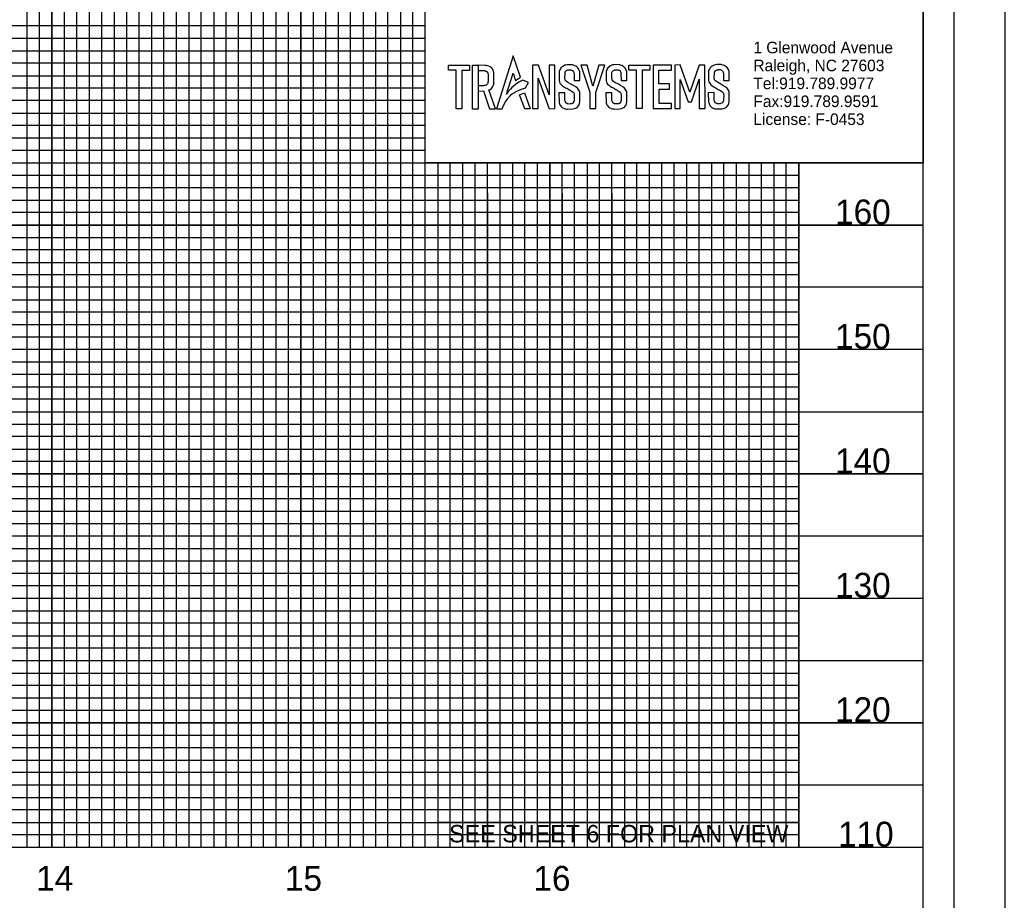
# Model space of a CAD drawing. Extents: x 1779926 to 1781626, y 618464 to 619564.
# Drawn here: x 1781230 to 1781626, y 619017.9 to 619371.7 of the extents above; entities that cross this region are included whole.
import ezdxf

# ---------------------------------------------------------------- set-up
doc = ezdxf.new("R2010")
doc.units = 0
for name, color, linetype in [('Default', 7, 'Continuous'), ('Exist Vertical Profile Horizontal Axis Label Major', 7, 'Continuous'), ('Exist Vertical Profile Vertical Axis Label', 7, 'Continuous'), ('Old_Level_2', 7, 'Continuous'), ('Old_Level_58', 7, 'Continuous'), ('Prop DSN Text', 7, 'Continuous'), ('Prop Grid Mask', 7, 'Continuous'), ('Sheet DOT Grid CELL', 7, 'Continuous'), ('Sheet Layout Profile Border Port 1', 7, 'Continuous'), ('Sheet Plot Border Inside CELL', 7, 'Continuous'), ('Sheet Plot Border Outside CELL', 7, 'Continuous'), ('Sheet Profile CELL', 7, 'Continuous'), ('Sheet Profile Grid Major CELL', 7, 'Continuous'), ('Sheet Profile Grid Middle CELL', 7, 'Continuous'), ('Sheet Profile Grid Minor CELL', 7, 'Continuous')]:
    doc.layers.add(name, color=color, linetype=linetype)

msp = doc.modelspace()

# ---------------------------------------------------------------- linework, layer by layer
at = {"layer": 'Default'}
for points in [[(1781428.26, 619357.23), (1781421.6, 619335.89), (1781423.82, 619335.9), (1781424.16, 619336.74), (1781424.73, 619337.9), (1781425.05, 619338.53), (1781425.42, 619339.07), (1781425.95, 619339.83), (1781426.27, 619340.3), (1781426.65, 619340.69), (1781427.03, 619341.08), (1781427.52, 619341.58), (1781427.93, 619341.85), (1781428.34, 619342.18), (1781428.9, 619342.5), (1781429.39, 619342.78), (1781430.61, 619343.35), (1781431.61, 619343.76), (1781433.25, 619344.32), (1781434.39, 619346.46), (1781432.21, 619347.42), (1781430.58, 619346.53), (1781429.2, 619345.63), (1781428.22, 619344.83), (1781427.7, 619344.41), (1781427.17, 619343.84), (1781426.63, 619343.27), (1781426.23, 619342.85), (1781425.85, 619342.2), (1781425.65, 619341.84), (1781428.27, 619350.22), (1781429.27, 619347.33), (1781431.17, 619348.58)], [(1781402.3, 619353.38), (1781410.76, 619353.39), (1781410.77, 619351.31), (1781407.66, 619351.31), (1781407.67, 619335.89), (1781405.32, 619335.89), (1781405.31, 619351.41), (1781402.33, 619351.41)], [(1781411.92, 619353.37), (1781414.23, 619353.38), (1781414.25, 619335.81), (1781411.93, 619335.81)], [(1781414.24, 619351.29), (1781416.62, 619351.29), (1781416.93, 619351.24), (1781417.33, 619351.08), (1781417.65, 619350.86), (1781417.88, 619350.59), (1781418.04, 619350.26), (1781418.16, 619350), (1781418.16, 619349.42), (1781418.17, 619346.93), (1781418.11, 619346.6), (1781418.03, 619346.16), (1781417.89, 619345.86), (1781417.69, 619345.6), (1781417.43, 619345.39), (1781417, 619345.24), (1781416.67, 619345.2), (1781416.35, 619345.15), (1781414.24, 619345.14), (1781414.25, 619343.03), (1781416.36, 619343.05), (1781418.73, 619335.88), (1781421.14, 619335.91), (1781418.49, 619343.45), (1781418.87, 619343.58), (1781419.41, 619343.98), (1781419.9, 619344.52), (1781420.25, 619345.15), (1781420.46, 619345.78), (1781420.45, 619345.97), (1781420.49, 619350.53), (1781420.28, 619351.28), (1781419.92, 619351.96), (1781419.51, 619352.43), (1781418.81, 619352.9), (1781418.14, 619353.13), (1781417.46, 619353.35), (1781417.05, 619353.35), (1781414.23, 619353.38)], [(1781436.03, 619353.41), (1781436.05, 619335.95), (1781438.28, 619335.95), (1781438.27, 619348.23), (1781442.72, 619335.93), (1781444.97, 619335.96), (1781444.95, 619353.46), (1781442.77, 619353.46), (1781442.79, 619341.48), (1781438.39, 619353.42)], [(1781452.73, 619347.24), (1781455.04, 619347.24), (1781455.04, 619350.72), (1781454.84, 619351.42), (1781454.56, 619352.01), (1781454.26, 619352.4), (1781453.89, 619352.76), (1781453.45, 619353.04), (1781453.03, 619353.21), (1781453.03, 619353.21), (1781452.57, 619353.41), (1781452.08, 619353.53), (1781451.76, 619353.61), (1781450.01, 619353.57), (1781449.48, 619353.48), (1781449.03, 619353.4), (1781448.57, 619353.16), (1781448.16, 619352.95), (1781447.77, 619352.67), (1781447.46, 619352.35), (1781447.22, 619351.99), (1781447.02, 619351.59), (1781446.77, 619350.9), (1781446.72, 619350.38), (1781446.72, 619347.21), (1781446.83, 619346.74), (1781447.06, 619346.24), (1781447.35, 619345.83), (1781447.65, 619345.52), (1781448.1, 619345.17), (1781448.55, 619344.83), (1781448.83, 619344.61), (1781449.32, 619344.38), (1781449.8, 619344.16), (1781450.19, 619343.9), (1781450.63, 619343.62), (1781451.16, 619343.35), (1781451.59, 619343.13), (1781452.02, 619342.82), (1781452.33, 619342.52), (1781452.58, 619342.28), (1781452.73, 619341.8), (1781452.83, 619341.5), (1781452.79, 619339.27), (1781452.63, 619338.78), (1781452.39, 619338.36), (1781452.06, 619338.07), (1781451.71, 619337.91), (1781451.36, 619337.84), (1781450.4, 619337.82), (1781450.08, 619337.91), (1781449.75, 619338.1), (1781449.42, 619338.3), (1781449.28, 619338.63), (1781449.14, 619338.97), (1781449.02, 619339.23), (1781448.99, 619342.35), (1781446.65, 619342.32), (1781446.69, 619338.61), (1781446.81, 619338.33), (1781447.08, 619337.46), (1781447.26, 619337.17), (1781447.51, 619336.85), (1781447.89, 619336.48), (1781448.19, 619336.29), (1781448.63, 619336.1), (1781448.79, 619336.04), (1781449.22, 619335.86), (1781449.75, 619335.8), (1781450.14, 619335.76), (1781452.29, 619335.82), (1781452.88, 619335.96), (1781453.71, 619336.33), (1781453.99, 619336.46), (1781454.61, 619337.25), (1781454.94, 619338.04), (1781455.1, 619338.75), (1781455.04, 619342.17), (1781455.04, 619342.64), (1781454.91, 619343.02), (1781454.71, 619343.37), (1781454.17, 619344.13), (1781453.47, 619344.69), (1781452.49, 619345.27), (1781451.75, 619345.71), (1781450.28, 619346.48), (1781449.53, 619347.04), (1781449.2, 619347.46), (1781449.12, 619347.74), (1781449.05, 619348.03), (1781449.09, 619350.46), (1781449.22, 619350.71), (1781449.34, 619350.97), (1781449.52, 619351.12), (1781449.75, 619351.32), (1781450.01, 619351.42), (1781450.27, 619351.53), (1781450.41, 619351.5), (1781450.43, 619351.58), (1781451.39, 619351.56), (1781451.67, 619351.45), (1781451.94, 619351.34), (1781452.22, 619351.23), (1781452.35, 619351.04), (1781452.53, 619350.76), (1781452.63, 619350.48), (1781452.72, 619350.21), (1781452.71, 619349.9)], [(1781458, 619353.42), (1781455.46, 619353.42), (1781459.08, 619342.54), (1781459.11, 619335.99), (1781461.5, 619336.01), (1781461.47, 619342.5), (1781465.13, 619353.46), (1781462.63, 619353.39), (1781460.33, 619345.05)], [(1781471.6, 619347.26), (1781473.91, 619347.26), (1781473.91, 619350.74), (1781473.71, 619351.44), (1781473.43, 619352.03), (1781473.13, 619352.42), (1781472.76, 619352.77), (1781472.32, 619353.06), (1781471.9, 619353.23), (1781471.9, 619353.23), (1781471.44, 619353.42), (1781470.96, 619353.55), (1781470.64, 619353.63), (1781468.89, 619353.59), (1781468.36, 619353.5), (1781467.9, 619353.42), (1781467.44, 619353.18), (1781467.03, 619352.97), (1781466.64, 619352.68), (1781466.33, 619352.37), (1781466.09, 619352.01), (1781465.89, 619351.61), (1781465.64, 619350.91), (1781465.59, 619350.4), (1781465.59, 619347.23), (1781465.7, 619346.75), (1781465.93, 619346.26), (1781466.22, 619345.85), (1781466.52, 619345.54), (1781466.97, 619345.19), (1781467.42, 619344.84), (1781467.71, 619344.62), (1781468.19, 619344.4), (1781468.67, 619344.17), (1781469.06, 619343.92), (1781469.5, 619343.63), (1781470.03, 619343.37), (1781470.46, 619343.15), (1781470.89, 619342.83), (1781471.2, 619342.54), (1781471.45, 619342.3), (1781471.61, 619341.82), (1781471.7, 619341.52), (1781471.67, 619339.28), (1781471.51, 619338.8), (1781471.26, 619338.38), (1781470.93, 619338.09), (1781470.58, 619337.93), (1781470.24, 619337.86), (1781469.27, 619337.84), (1781468.95, 619337.93), (1781468.62, 619338.12), (1781468.29, 619338.31), (1781468.15, 619338.65), (1781468.01, 619338.98), (1781467.9, 619339.25), (1781467.86, 619342.36), (1781465.52, 619342.34), (1781465.57, 619338.63), (1781465.68, 619338.34), (1781465.95, 619337.48), (1781466.13, 619337.19), (1781466.38, 619336.87), (1781466.76, 619336.5), (1781467.07, 619336.3), (1781467.5, 619336.12), (1781467.66, 619336.05), (1781468.09, 619335.87), (1781468.62, 619335.82), (1781469.02, 619335.78), (1781471.16, 619335.84), (1781471.75, 619335.98), (1781472.58, 619336.35), (1781472.86, 619336.48), (1781473.48, 619337.27), (1781473.81, 619338.05), (1781473.97, 619338.76), (1781473.92, 619342.19), (1781473.91, 619342.66), (1781473.78, 619343.03), (1781473.59, 619343.39), (1781473.05, 619344.15), (1781472.34, 619344.7), (1781471.36, 619345.28), (1781470.62, 619345.73), (1781469.16, 619346.49), (1781468.4, 619347.06), (1781468.07, 619347.48), (1781468, 619347.76), (1781467.92, 619348.05), (1781467.96, 619350.48), (1781468.09, 619350.73), (1781468.21, 619350.99), (1781468.39, 619351.14), (1781468.62, 619351.33), (1781468.88, 619351.44), (1781469.14, 619351.55), (1781469.29, 619351.52), (1781469.3, 619351.59), (1781470.26, 619351.58), (1781470.54, 619351.47), (1781470.81, 619351.36), (1781471.09, 619351.25), (1781471.22, 619351.06), (1781471.41, 619350.78), (1781471.5, 619350.5), (1781471.59, 619350.23), (1781471.58, 619349.92)], [(1781474.76, 619353.45), (1781483.22, 619353.45), (1781483.23, 619351.38), (1781480.12, 619351.38), (1781480.13, 619335.96), (1781477.78, 619335.95), (1781477.77, 619351.48), (1781474.79, 619351.48)], [(1781491.83, 619353.45), (1781484.44, 619353.45), (1781484.46, 619336.02), (1781491.93, 619336.03), (1781491.93, 619338), (1781486.88, 619337.99), (1781486.88, 619343.84), (1781491.1, 619343.84), (1781491.09, 619345.91), (1781486.84, 619345.91), (1781486.84, 619351.41), (1781491.85, 619351.41)], [(1781499.21, 619342.6), (1781495.39, 619353.53), (1781493.18, 619353.42), (1781493.27, 619335.96), (1781495.38, 619335.97), (1781495.32, 619347.65), (1781498.59, 619338.66), (1781499.93, 619338.63), (1781503, 619347.76), (1781503.05, 619336.04), (1781505.33, 619336.05), (1781505.26, 619353.47), (1781502.96, 619353.46)], [(1781512.73, 619347.3), (1781515.04, 619347.3), (1781515.04, 619350.77), (1781514.84, 619351.48), (1781514.56, 619352.07), (1781514.26, 619352.46), (1781513.89, 619352.81), (1781513.46, 619353.09), (1781513.03, 619353.27), (1781513.03, 619353.27), (1781512.57, 619353.46), (1781512.09, 619353.58), (1781511.77, 619353.66), (1781510.02, 619353.63), (1781509.49, 619353.54), (1781509.03, 619353.46), (1781508.57, 619353.22), (1781508.17, 619353.01), (1781507.77, 619352.72), (1781507.46, 619352.41), (1781507.22, 619352.04), (1781507.03, 619351.65), (1781506.77, 619350.95), (1781506.72, 619350.44), (1781506.72, 619347.27), (1781506.84, 619346.79), (1781507.07, 619346.3), (1781507.35, 619345.89), (1781507.65, 619345.58), (1781508.1, 619345.23), (1781508.55, 619344.88), (1781508.84, 619344.66), (1781509.32, 619344.44), (1781509.8, 619344.21), (1781510.19, 619343.96), (1781510.64, 619343.67), (1781511.16, 619343.41), (1781511.6, 619343.19), (1781512.03, 619342.87), (1781512.34, 619342.58), (1781512.59, 619342.34), (1781512.74, 619341.86), (1781512.83, 619341.56), (1781512.8, 619339.32), (1781512.64, 619338.84), (1781512.39, 619338.42), (1781512.06, 619338.13), (1781511.71, 619337.97), (1781511.37, 619337.9), (1781510.41, 619337.88), (1781510.08, 619337.97), (1781509.76, 619338.16), (1781509.43, 619338.35), (1781509.28, 619338.69), (1781509.14, 619339.02), (1781509.03, 619339.29), (1781508.99, 619342.4), (1781506.65, 619342.37), (1781506.7, 619338.66), (1781506.82, 619338.38), (1781507.09, 619337.52), (1781507.26, 619337.23), (1781507.51, 619336.91), (1781507.89, 619336.53), (1781508.2, 619336.34), (1781508.63, 619336.16), (1781508.79, 619336.09), (1781509.22, 619335.91), (1781509.76, 619335.86), (1781510.15, 619335.82), (1781512.29, 619335.87), (1781512.89, 619336.01), (1781513.71, 619336.39), (1781513.99, 619336.51), (1781514.61, 619337.31), (1781514.95, 619338.09), (1781515.1, 619338.8), (1781515.05, 619342.22), (1781515.04, 619342.7), (1781514.91, 619343.07), (1781514.72, 619343.43), (1781514.18, 619344.19), (1781513.47, 619344.74), (1781512.5, 619345.32), (1781511.75, 619345.77), (1781510.29, 619346.53), (1781509.53, 619347.09), (1781509.21, 619347.52), (1781509.13, 619347.8), (1781509.05, 619348.08), (1781509.1, 619350.51), (1781509.22, 619350.77), (1781509.34, 619351.02), (1781509.52, 619351.18), (1781509.75, 619351.37), (1781510.01, 619351.48), (1781510.27, 619351.59), (1781510.42, 619351.56), (1781510.43, 619351.63), (1781511.39, 619351.62), (1781511.67, 619351.51), (1781511.95, 619351.4), (1781512.22, 619351.29), (1781512.35, 619351.09), (1781512.54, 619350.82), (1781512.63, 619350.54), (1781512.72, 619350.26), (1781512.72, 619349.96)], [(1781430.87, 619341.52), (1781432.79, 619342.29), (1781435.06, 619335.85), (1781432.95, 619335.93)]]:
    msp.add_lwpolyline(points, close=True, dxfattribs=at)
at = {"layer": 'Old_Level_58'}
for points in [[(1781392.9, 619378.14), (1781592.96, 619378.14), (1781592.96, 619314.19), (1781392.9, 619314.19)], [(1781392.96, 619378.14), (1781592.96, 619378.14), (1781592.96, 619314.19), (1781392.96, 619314.19)]]:
    msp.add_lwpolyline(points, close=True, dxfattribs=at)
at = {"layer": 'Prop Grid Mask'}
msp.add_lwpolyline([(1781542.96, 619049.19), (1781397.96, 619049.19), (1781397.96, 619039.19), (1781542.96, 619039.19)], close=True, dxfattribs=at)
at = {"layer": 'Sheet DOT Grid CELL'}
for p, q in [((1781242.96, 619039.19), (1781242.96, 619539.19)), ((1781292.96, 619039.19), (1781292.96, 619539.19)), ((1781342.96, 619039.19), (1781342.96, 619539.19)), ((1781392.96, 619039.19), (1781392.96, 619401.64)), ((1781392.91, 619339.19), (1780092.96, 619339.19)), ((1781442.96, 619039.19), (1781442.96, 619314.19)), ((1781492.96, 619039.19), (1781492.96, 619314.19)), ((1781542.96, 619039.19), (1781542.96, 619314.19)), ((1781592.96, 619289.19), (1780092.96, 619289.19)), ((1781592.96, 619239.19), (1780092.96, 619239.19)), ((1781592.96, 619189.19), (1780092.96, 619189.19)), ((1781592.96, 619139.19), (1780092.96, 619139.19)), ((1781592.96, 619089.19), (1780092.96, 619089.19))]:
    msp.add_line(p, q, dxfattribs=at)
at = {"layer": 'Sheet Layout Profile Border Port 1'}
msp.add_line((1781542.96, 619049.19), (1781542.96, 619099.19), dxfattribs=at)
for points in [[(1781542.96, 619099.19), (1781542.96, 619314.19), (1781392.91, 619314.19), (1781392.96, 619539.19), (1780142.96, 619539.19), (1780142.96, 619039.19), (1781542.96, 619039.19), (1781542.96, 619049.19)], [(1780142.96, 619378.14), (1780142.96, 619039.19), (1781542.96, 619039.19), (1781542.96, 619314.19)]]:
    msp.add_lwpolyline(points, dxfattribs=at)
at = {"layer": 'Sheet Plot Border Inside CELL'}
msp.add_lwpolyline([(1779938.96, 618486.64), (1781605.46, 618486.64), (1781605.46, 619541.74), (1779938.96, 619541.74)], close=True, dxfattribs=at)
at = {"layer": 'Sheet Plot Border Outside CELL'}
msp.add_lwpolyline([(1779925.96, 618464.19), (1781625.96, 618464.19), (1781625.96, 619564.19), (1779925.96, 619564.19)], close=True, dxfattribs=at)
at = {"layer": 'Sheet Profile CELL'}
msp.add_line((1780092.96, 619039.19), (1781592.96, 619039.19), dxfattribs=at)
msp.add_lwpolyline([(1781592.96, 619539.19), (1780092.96, 619539.19), (1780092.96, 618489.19), (1781592.96, 618489.19)], close=True, dxfattribs=at)
at = {"layer": 'Sheet Profile Grid Major CELL'}
for points in [[(1780842.96, 619039.19), (1780892.96, 619039.19), (1780892.96, 619539.19), (1780942.96, 619539.19), (1780942.96, 619039.19), (1780992.96, 619039.19), (1780992.96, 619539.19), (1781042.96, 619539.19), (1781042.96, 619039.19), (1781092.96, 619039.19), (1781092.96, 619539.19), (1781142.96, 619539.19), (1781142.96, 619039.19), (1781192.96, 619039.19), (1781192.96, 619539.19), (1781242.96, 619539.19), (1781242.96, 619039.19), (1781292.96, 619039.19), (1781292.96, 619539.19), (1781342.96, 619539.19), (1781342.96, 619039.19), (1781392.96, 619039.19), (1781392.96, 619539.19), (1781419.26, 619539.19)], [(1781542.96, 619314.19), (1781542.96, 619039.19), (1781592.96, 619039.19), (1781592.96, 619389.19)], [(1781392.96, 619339.19), (1780092.96, 619339.19), (1780092.96, 619289.19), (1781592.96, 619289.19)], [(1781442.96, 619314.19), (1781442.96, 619039.19), (1781492.96, 619039.19), (1781492.96, 619039.19), (1781492.96, 619314.19)], [(1781592.96, 619239.19), (1780092.96, 619239.19), (1780092.96, 619189.19), (1781592.96, 619189.19)], [(1781592.96, 619139.19), (1780092.96, 619139.19), (1780092.96, 619139.19), (1780092.96, 619089.19), (1781592.96, 619089.19)]]:
    msp.add_lwpolyline(points, dxfattribs=at)
at = {"layer": 'Sheet Profile Grid Middle CELL'}
for points in [[(1781217.96, 619539.19), (1781267.96, 619539.19), (1781267.96, 619039.19), (1781317.96, 619039.19), (1781317.96, 619539.19), (1781367.96, 619539.19), (1781367.96, 619039.19), (1781417.96, 619039.19), (1781417.96, 619314.19)], [(1781392.91, 619364.19), (1780092.96, 619364.19), (1780092.96, 619314.19), (1781417.96, 619314.19)], [(1781417.96, 619314.19), (1781592.96, 619314.19)], [(1781417.96, 619301.99), (1781417.96, 619039.19), (1781467.96, 619039.19), (1781467.96, 619314.19)], [(1781467.96, 619301.99), (1781467.96, 619039.19), (1781517.96, 619039.19), (1781517.96, 619314.19)], [(1781592.96, 619264.19), (1780092.96, 619264.19), (1780092.96, 619214.19), (1781592.96, 619214.19)], [(1781592.96, 619164.19), (1780092.96, 619164.19), (1780092.96, 619114.19), (1781592.96, 619114.19)], [(1781592.96, 619064.19), (1780092.96, 619064.19)]]:
    msp.add_lwpolyline(points, dxfattribs=at)
at = {"layer": 'Sheet Profile Grid Minor CELL'}
for p, q in [((1781392.91, 619354.19), (1780142.96, 619354.19)), ((1780142.96, 619349.19), (1781392.91, 619349.19)), ((1781392.91, 619329.19), (1780142.96, 619329.19)), ((1780142.96, 619324.19), (1781392.91, 619324.19)), ((1781542.96, 619304.19), (1780142.96, 619304.19)), ((1780142.96, 619299.19), (1781542.96, 619299.19)), ((1781542.96, 619294.19), (1780142.96, 619294.19)), ((1780142.96, 619284.19), (1781542.96, 619284.19)), ((1781542.96, 619279.19), (1780142.96, 619279.19)), ((1780142.96, 619274.19), (1781542.96, 619274.19)), ((1781542.96, 619269.19), (1780142.96, 619269.19)), ((1780142.96, 619259.19), (1781542.96, 619259.19)), ((1781542.96, 619254.19), (1780142.96, 619254.19)), ((1780142.96, 619249.19), (1781542.96, 619249.19)), ((1781542.96, 619244.19), (1780142.96, 619244.19)), ((1780142.96, 619234.19), (1781542.96, 619234.19)), ((1781542.96, 619229.19), (1780142.96, 619229.19)), ((1780142.96, 619224.19), (1781542.96, 619224.19)), ((1781542.96, 619219.19), (1780142.96, 619219.19)), ((1780142.96, 619209.19), (1781542.96, 619209.19)), ((1781542.96, 619204.19), (1780142.96, 619204.19)), ((1780142.96, 619199.19), (1781542.96, 619199.19)), ((1781542.96, 619194.19), (1780142.96, 619194.19)), ((1780142.96, 619184.19), (1781542.96, 619184.19)), ((1781542.96, 619179.19), (1780142.96, 619179.19)), ((1780142.96, 619174.19), (1781542.96, 619174.19)), ((1781542.96, 619169.19), (1780142.96, 619169.19)), ((1780142.96, 619159.19), (1781542.96, 619159.19)), ((1781542.96, 619154.19), (1780142.96, 619154.19)), ((1781542.96, 619149.19), (1780142.96, 619149.19)), ((1781542.96, 619144.19), (1780142.96, 619144.19)), ((1780142.96, 619134.19), (1781542.96, 619134.19)), ((1781542.96, 619129.19), (1780142.96, 619129.19)), ((1780142.96, 619124.19), (1781542.96, 619124.19)), ((1781542.96, 619119.19), (1780142.96, 619119.19)), ((1780142.96, 619109.19), (1781542.96, 619109.19)), ((1781542.96, 619104.19), (1780142.96, 619104.19)), ((1780142.96, 619099.19), (1781542.96, 619099.19)), ((1781542.96, 619094.19), (1780142.96, 619094.19)), ((1780142.96, 619084.19), (1781542.96, 619084.19)), ((1781542.96, 619079.19), (1780142.96, 619079.19)), ((1780142.96, 619074.19), (1781542.96, 619074.19)), ((1781542.96, 619069.19), (1780142.96, 619069.19)), ((1780142.96, 619059.19), (1781542.96, 619059.19)), ((1781542.96, 619054.19), (1780142.96, 619054.19)), ((1780142.96, 619049.19), (1781542.96, 619049.19))]:
    msp.add_line(p, q, dxfattribs=at)
for points in [[(1781227.96, 619539.19), (1781232.96, 619539.19), (1781232.96, 619039.19), (1781237.96, 619039.19), (1781237.96, 619539.19), (1781247.96, 619539.19), (1781247.96, 619039.19), (1781252.96, 619039.19), (1781252.96, 619539.19), (1781257.96, 619539.19), (1781257.96, 619039.19), (1781262.96, 619039.19), (1781262.96, 619539.19), (1781272.96, 619539.19), (1781272.96, 619039.19), (1781277.96, 619039.19), (1781277.96, 619539.19), (1781282.96, 619539.19), (1781282.96, 619039.19)], [(1781282.96, 619039.19), (1781287.96, 619039.19), (1781287.96, 619539.19)], [(1781297.96, 619539.19), (1781297.96, 619039.19), (1781302.96, 619039.19), (1781302.96, 619539.19)], [(1781307.96, 619539.19), (1781307.96, 619039.19), (1781312.96, 619039.19), (1781312.96, 619539.19)], [(1781322.96, 619539.19), (1781322.96, 619039.19), (1781327.96, 619039.19), (1781327.96, 619539.19)], [(1781332.96, 619539.19), (1781332.96, 619039.19), (1781337.96, 619039.19), (1781337.96, 619539.19)], [(1781347.96, 619539.19), (1781347.96, 619039.19), (1781352.96, 619039.19), (1781352.96, 619539.19)], [(1781357.96, 619539.19), (1781357.96, 619039.19), (1781362.96, 619039.19), (1781362.96, 619539.19)], [(1781372.96, 619539.19), (1781372.96, 619039.19), (1781377.96, 619039.19), (1781377.96, 619539.19)], [(1781382.96, 619539.19), (1781382.96, 619039.19), (1781387.96, 619039.19), (1781387.96, 619539.19)], [(1781392.91, 619369.19), (1780142.96, 619369.19), (1780142.96, 619359.19), (1781392.91, 619359.19)], [(1781392.91, 619344.19), (1780142.96, 619344.19), (1780142.96, 619334.19), (1781392.91, 619334.19)], [(1781392.91, 619319.19), (1780142.96, 619319.19), (1780142.96, 619309.19), (1781542.96, 619309.19)], [(1781397.96, 619314.19), (1781397.96, 619039.19), (1781402.96, 619039.19), (1781402.96, 619314.19)], [(1781407.96, 619314.19), (1781407.96, 619039.19), (1781412.96, 619039.19), (1781412.96, 619314.19)], [(1781422.96, 619314.19), (1781422.96, 619039.19), (1781422.96, 619039.19), (1781427.96, 619039.19), (1781432.96, 619039.19), (1781432.96, 619314.19)], [(1781427.96, 619314.19), (1781427.96, 619039.19)], [(1781437.94, 619314.19), (1781437.86, 619039.24), (1781442.86, 619039.24), (1781447.96, 619039.19), (1781447.96, 619314.19)], [(1781447.96, 619301.99), (1781447.96, 619039.19), (1781452.96, 619039.19), (1781452.96, 619314.19)], [(1781457.96, 619314.19), (1781457.96, 619039.19), (1781462.96, 619039.19), (1781462.96, 619314.19)], [(1781472.96, 619314.19), (1781472.96, 619039.19), (1781477.96, 619039.19), (1781477.96, 619314.19)], [(1781482.96, 619314.19), (1781482.96, 619039.19), (1781487.96, 619039.19), (1781487.96, 619314.19)], [(1781497.96, 619314.19), (1781497.96, 619039.19), (1781502.96, 619039.19), (1781502.96, 619314.19)], [(1781507.96, 619314.19), (1781507.96, 619039.19), (1781512.96, 619039.19), (1781512.96, 619314.19)], [(1781522.96, 619314.19), (1781522.96, 619039.19), (1781527.96, 619039.19), (1781527.96, 619314.19)], [(1781532.96, 619314.19), (1781532.96, 619039.19), (1781537.96, 619039.19), (1781537.96, 619314.19)], [(1781542.96, 619044.19), (1780142.96, 619044.19)]]:
    msp.add_lwpolyline(points, dxfattribs=at)

# ---------------------------------------------------------------- texts
at = {"layer": 'Exist Vertical Profile Horizontal Axis Label Major'}
for s, p in [('14', (1781236.66, 619021.69)), ('15', (1781336.59, 619021.69)), ('16', (1781436.42, 619021.69))]:
    msp.add_text(s, height=10, dxfattribs=at).set_placement(p)
at = {"layer": 'Exist Vertical Profile Vertical Axis Label'}
for s, p in [('160', (1781557.59, 619289.44)), ('150', (1781557.59, 619239.44)), ('140', (1781557.59, 619189.44)), ('130', (1781557.59, 619139.44)), ('120', (1781557.59, 619089.44)), ('110', (1781558.79, 619039.44))]:
    msp.add_text(s, height=10, dxfattribs=at).set_placement(p)
at = {"layer": 'Old_Level_2'}
for s, p in [('1 Glenwood Avenue', (1781524.76, 619358.18)), ('Raleigh, NC 27603', (1781524.76, 619350.98)), ('Tel:919.789.9977 ', (1781524.76, 619343.79)), ('Fax:919.789.9591', (1781524.76, 619336.59)), ('License: F-0453', (1781524.76, 619329.39))]:
    msp.add_text(s, height=4.6576, rotation=360, dxfattribs=at).set_placement(p)
at = {"layer": 'Prop DSN Text'}
msp.add_text('SEE SHEET 6 FOR PLAN VIEW', height=7, dxfattribs=at).set_placement((1781402.54, 619041.14))

doc.saveas('drawing.dxf')
